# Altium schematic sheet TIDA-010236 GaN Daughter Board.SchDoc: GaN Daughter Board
size A3; DrawnBy: Hely Zhang; Engineer: Hely Zhang; DocumentNumber: 1; Revision: B; SheetNumber: 1; SheetTotal: 1; PageSetup: Record=PageOptions¦CenterHorizontal=True¦CenterVertical=True¦PrintScale=0.69¦XCorrection=1.00¦YCorrection=1.00¦PrintKind=0¦BorderSize=5000000¦LeftOffset=0¦BottomOffset=0¦Orientation=2¦PaperLength=1000¦PaperWidth=1000¦Scale=100¦PaperSource=15¦PrintQuality=600¦MediaType=1¦DitherType=10¦PaperKind=Letter¦PrintScaleMode=1
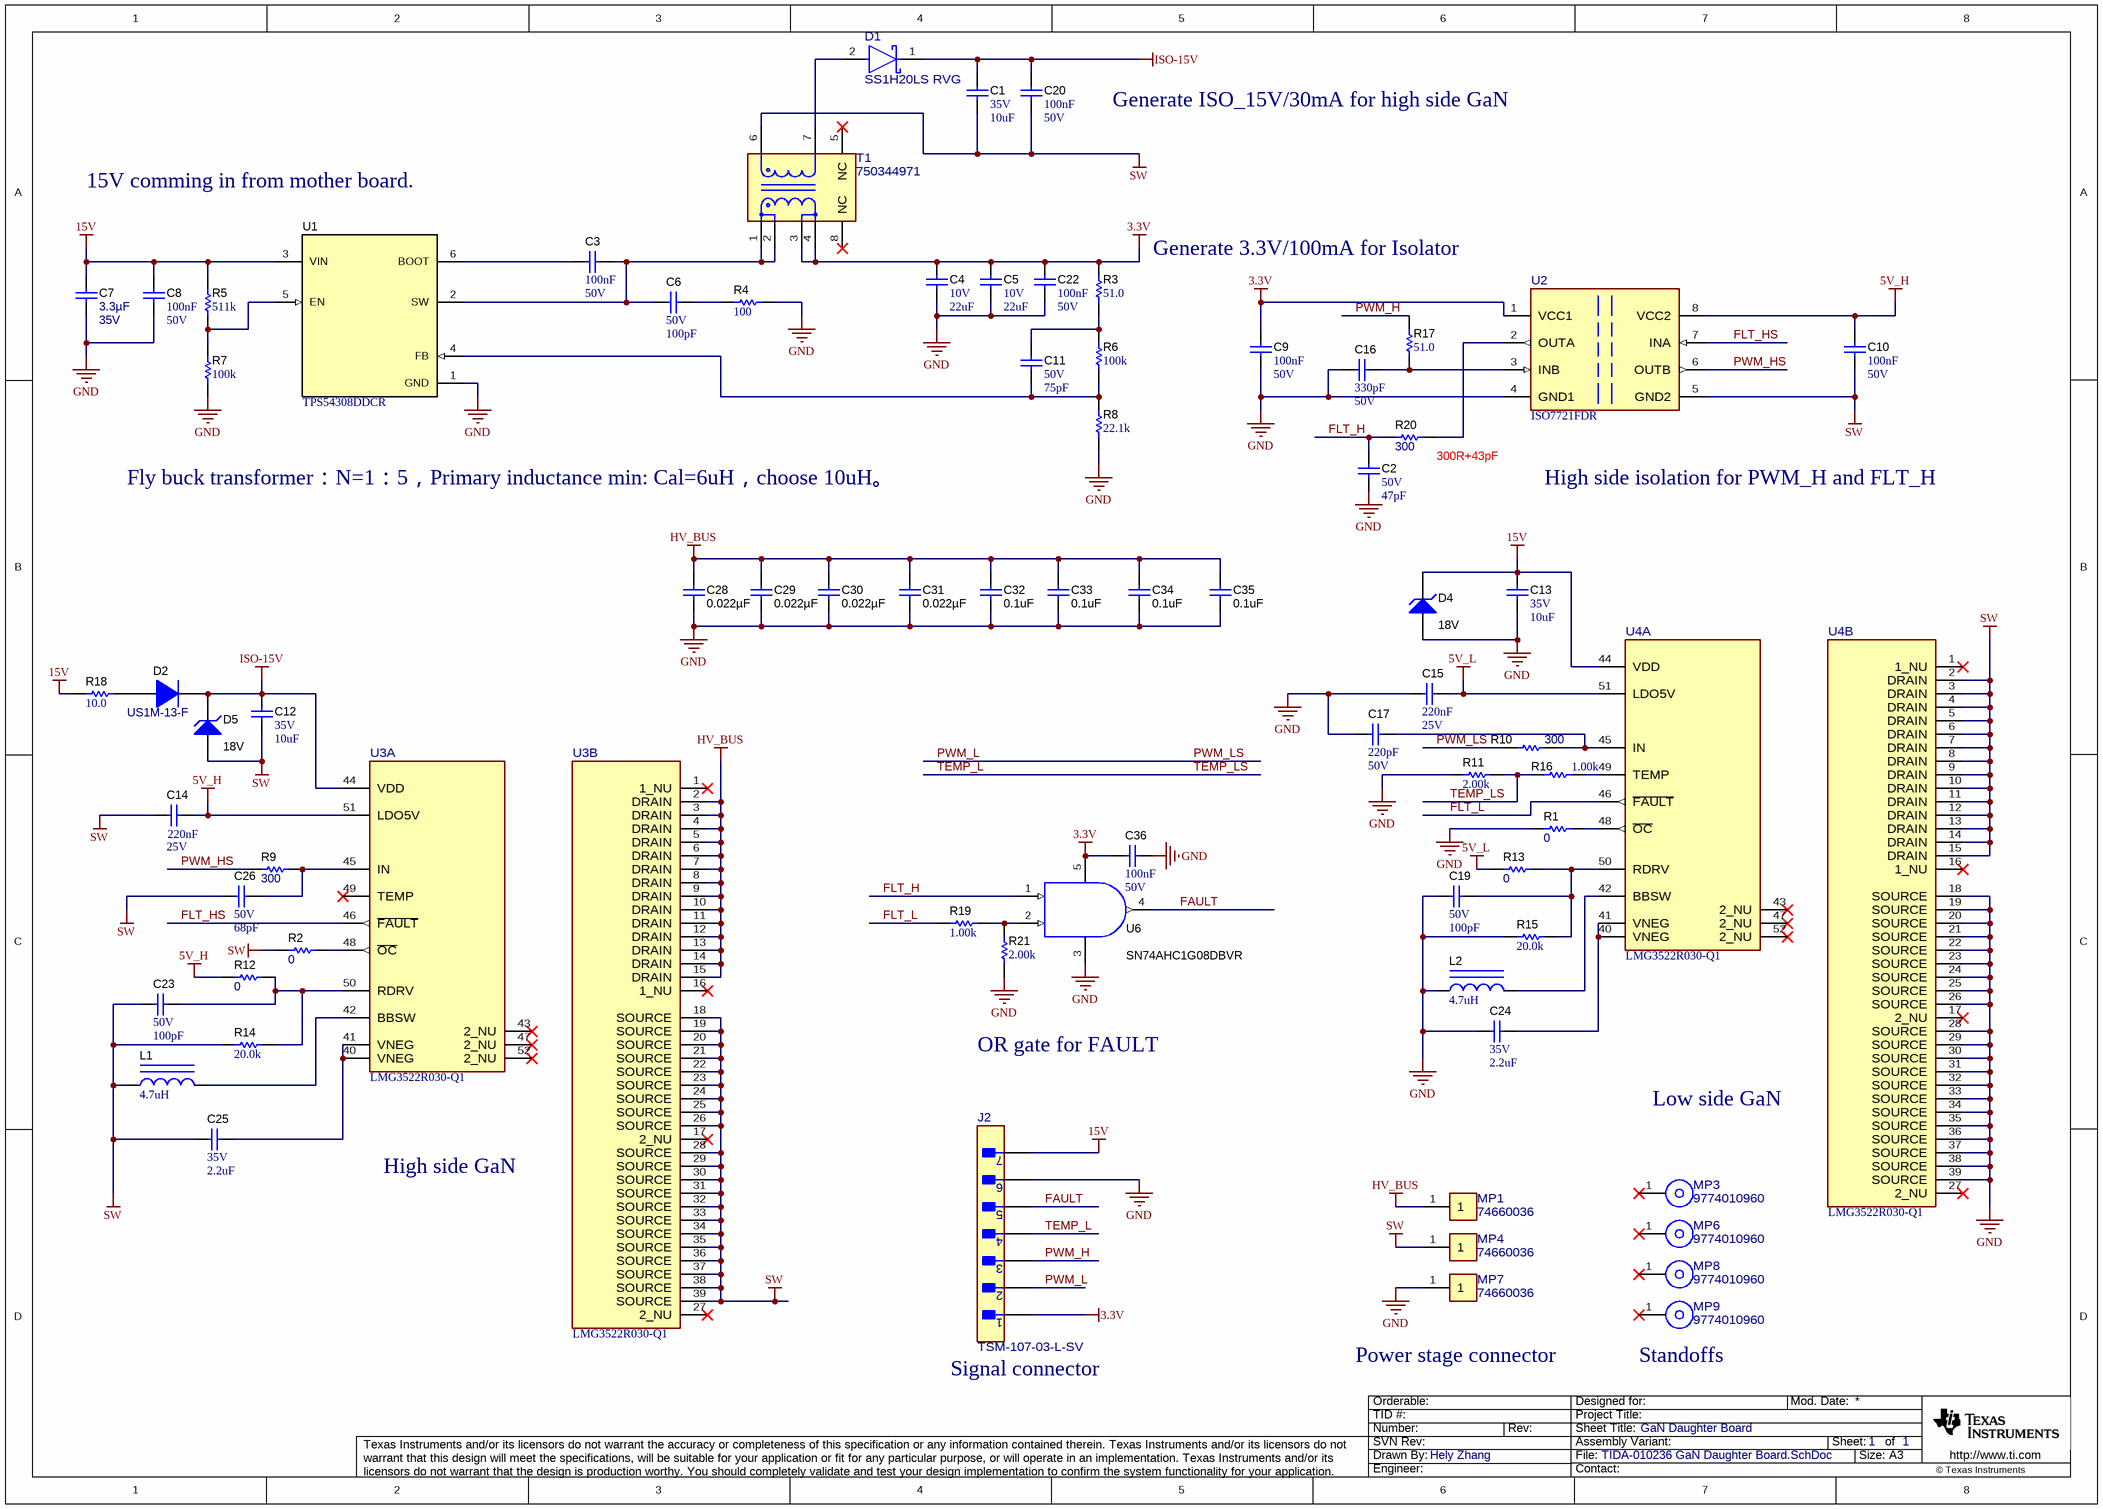
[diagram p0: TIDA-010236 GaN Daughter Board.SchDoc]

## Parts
C1  VDC_V: 35V  ValueDisplayed: 10uF  [1206_190]  (hidden comment: C3216X7R1V106M160AC)
C2  VDC_V: 50V  ValueDisplayed: 47pF  [0603]  (hidden comment: GRM1885C1H470JA01D)
C3  Cap_F: 100nF  VDC_V: 50V  [0603]  (hidden comment: 06035C104JAT2A)
C4  VDC_V: 10V  ValueDisplayed: 22uF  [1206_180]  (hidden comment: GRM31CR71A226ME15L)
C5  VDC_V: 10V  ValueDisplayed: 22uF  [1206_180]  (hidden comment: GRM31CR71A226ME15L)
C6  VDC_V: 50V  ValueDisplayed: 100pF  [0603]  (hidden comment: GRM1885C1H101JA01D)
C7  Cap_F: 3.3µF  VDC_V: 35V  [0805_HV]  (hidden comment: CGA4J1X7R1V335K125AC)
C8  Cap_F: 100nF  VDC_V: 50V  [0603]  (hidden comment: 06035C104JAT2A)
C9  Cap_F: 100nF  VDC_V: 50V  [0603]  (hidden comment: 06035C104JAT2A)
C10  Cap_F: 100nF  VDC_V: 50V  [0603]  (hidden comment: 06035C104JAT2A)
C11  VDC_V: 50V  ValueDisplayed: 75pF  [0603]  (hidden comment: GRM1885C1H750JA01D)
C12  VDC_V: 35V  ValueDisplayed: 10uF  [1206_190]  (hidden comment: C3216X7R1V106M160AC)
C13  VDC_V: 35V  ValueDisplayed: 10uF  [1206_190]  (hidden comment: C3216X7R1V106M160AC)
C14  Cap_F: 220nF  VDC_V: 25V  [0603]  (hidden comment: GRM188R71E224KA88D)
C15  Cap_F: 220nF  VDC_V: 25V  [0603]  (hidden comment: GRM188R71E224KA88D)
C16  Cap_F: 330pF  VDC_V: 50V  [0603]  (hidden comment: C0603C331K5RACTU)
C17  Cap_F: 220pF  VDC_V: 50V  [0603]  (hidden comment: GRM188R71H221KA01D)
C19  VDC_V: 50V  ValueDisplayed: 100pF  [0603]  (hidden comment: GRM1885C1H101JA01D)
C20  Cap_F: 100nF  VDC_V: 50V  [0603]  (hidden comment: 06035C104JAT2A)
C22  Cap_F: 100nF  VDC_V: 50V  [0603]  (hidden comment: 06035C104JAT2A)
C23  VDC_V: 50V  ValueDisplayed: 100pF  [0603]  (hidden comment: GRM1885C1H101JA01D)
C24  VDC_V: 35V  ValueDisplayed: 2.2uF  [0603]  (hidden comment: GRM188R6YA225KA12D)
C25  VDC_V: 35V  ValueDisplayed: 2.2uF  [0603]  (hidden comment: GRM188R6YA225KA12D)
C26  VDC_V: 50V  ValueDisplayed: 68pF  [0603]  (hidden comment: GCM1885C1H680JA16D)
C28  ValueDisplayed: 0.022µF  [1206_190]  (hidden comment: C1206C223KDRACTU)
C29  ValueDisplayed: 0.022µF  [1206_190]  (hidden comment: C1206C223KDRACTU)
C30  ValueDisplayed: 0.022µF  [1206_190]  (hidden comment: C1206C223KDRACTU)
C31  ValueDisplayed: 0.022µF  [1206_190]  (hidden comment: C1206C223KDRACTU)
C32  ValueDisplayed: 0.1uF  [1812_254]  (hidden comment: C1812W104KDRACTU)
C33  ValueDisplayed: 0.1uF  [1812_254]  (hidden comment: C1812W104KDRACTU)
C34  ValueDisplayed: 0.1uF  [1812_254]  (hidden comment: C1812W104KDRACTU)
C35  ValueDisplayed: 0.1uF  [1812_254]  (hidden comment: C1812W104KDRACTU)
C36  Cap_F: 100nF  VDC_V: 50V  [0603]  (hidden comment: 06035C104JAT2A)
D1  SS1H20LS RVG  [FP-SS1H20LS RVG_SOD123HE-MFG]
D2  US1M-13-F  [SMA]
D4  value 18V  [SOD-123]  (hidden comment: BZT52C18-7-F)
D5  value 18V  [SOD-123]  (hidden comment: BZT52C18-7-F)
J2  TSM-107-03-L-SV  [FP-TSM-107-03-L-SV_HDR7-MFG]
L1  ValueDisplayed: 4.7uH  [DFE252010C]  (hidden comment: 1269AS-H-4R7M=P2)
L2  ValueDisplayed: 4.7uH  [DFE252010C]  (hidden comment: 1269AS-H-4R7M=P2)
MP1  74660036  [FP-74660036_SMT_BUSH-MFG]
MP3  9774010960  [FP-9774010960_SPACER_ROUND-MFG]
MP4  74660036  [FP-74660036_SMT_BUSH-MFG]
MP6  9774010960  [FP-9774010960_SPACER_ROUND-MFG]
MP7  74660036  [FP-74660036_SMT_BUSH-MFG]
MP8  9774010960  [FP-9774010960_SPACER_ROUND-MFG]
MP9  9774010960  [FP-9774010960_SPACER_ROUND-MFG]
R1  ValueDisplayed: 0  [0402]  (hidden comment: RC0402JR-070RL)
R2  ValueDisplayed: 0  [0402]  (hidden comment: RC0402JR-070RL)
R3  ValueDisplayed: 51.0  [0603]  (hidden comment: RC0603FR-0751RL)
R4  ValueDisplayed: 100  [0603]  (hidden comment: RC0603FR-07100RL)
R5  ValueDisplayed: 511k  [0603]  (hidden comment: RC0603FR-07511KL)
R6  ValueDisplayed: 100k  [0603]  (hidden comment: RC0603FR-07100KL)
R7  ValueDisplayed: 100k  [0603]  (hidden comment: RC0603FR-07100KL)
R8  ValueDisplayed: 22.1k  [0603]  (hidden comment: RC0603FR-0722K1L)
R9  ValueDisplayed: 300  [0603]  (hidden comment: RC0603FR-07300RL)
R10  ValueDisplayed: 300  [0603]  (hidden comment: RC0603FR-07300RL)
R11  ValueDisplayed: 2.00k  [0603]  (hidden comment: RC0603FR-072KL)
R12  ValueDisplayed: 0  [0402]  (hidden comment: RC0402JR-070RL)
R13  ValueDisplayed: 0  [0402]  (hidden comment: RC0402JR-070RL)
R14  ValueDisplayed: 20.0k  [0603]  (hidden comment: RC0603FR-0720KL)
R15  ValueDisplayed: 20.0k  [0603]  (hidden comment: RC0603FR-0720KL)
R16  ValueDisplayed: 1.00k  [0603]  (hidden comment: RC0603FR-071KL)
R17  ValueDisplayed: 51.0  [0603]  (hidden comment: RC0603FR-0751RL)
R18  ValueDisplayed: 10.0  [1206]  (hidden comment: RC1206FR-0710RL)
R19  ValueDisplayed: 1.00k  [0603]  (hidden comment: RC0603FR-071KL)
R20  ValueDisplayed: 300  [0603]  (hidden comment: RC0603FR-07300RL)
R21  ValueDisplayed: 2.00k  [0603]  (hidden comment: RC0603FR-072KL)
T1  750344971  [FP-750344971_SMT_XFRMR_14MM0_10MM0-MFG]
U1  TPS54308DDCR  [DDC0006A_N]
U2  ISO7721FDR  [D0008A-MFG]
U3  LMG3522R030-Q1  [RQS0052C-C01-MFG]  (parts A,B of 2)
U4  LMG3522R030-Q1  [RQS0052C-C01-MFG]  (parts A,B of 2)
U6  SN74AHC1G08DBVR  [DBV0005A_N]

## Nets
3.3V: C4.1 C5.1 C9.1 C22.1 C36.1 J2.1 R3.2 T1.3 T1.4 U2.1(VCC1) U6.5(V+)
5V_H: C10.1 C14.2 R12.1 U2.8(VCC2) U3.51(LDO5V)
5V_L: C15.2 R13.1 U4.51(LDO5V)
15V: C7.1 C8.1 C13.1 D4.1(K) J2.7 R5.2 R18.1 U1.3(VIN) U4.44(VDD)
GND: C2.2 C4.2 C5.2 C7.2 C8.2 C9.2 C13.2 C15.1 C16.2 C17.2 C19.2 C22.2 C24.2 C28.2 C29.2 C30.2 C31.2 C32.2 C33.2 C34.2 C35.2 C36.2 D4.2(A) J2.6 L2.1 MP7.1 R1.1 R4.2 R7.1 R8.1 R11.2 R15.1 R21.1 U1.1(GND) U2.4(GND1) U4.18(SOURCE) U4.19(SOURCE) U4.20(SOURCE) U4.21(SOURCE) U4.22(SOURCE) U4.23(SOURCE) U4.24(SOURCE) U4.25(SOURCE) U4.26(SOURCE) U4.28(SOURCE) U4.29(SOURCE) U4.30(SOURCE) U4.31(SOURCE) U4.32(SOURCE) U4.33(SOURCE) U4.34(SOURCE) U4.35(SOURCE) U4.36(SOURCE) U4.37(SOURCE) U4.38(SOURCE) U4.39(SOURCE) U6.3(V-)
HV_BUS: C28.1 C29.1 C30.1 C31.1 C32.1 C33.1 C34.1 C35.1 MP1.1 U3.2(DRAIN) U3.3(DRAIN) U3.4(DRAIN) U3.5(DRAIN) U3.6(DRAIN) U3.7(DRAIN) U3.8(DRAIN) U3.9(DRAIN) U3.10(DRAIN) U3.11(DRAIN) U3.12(DRAIN) U3.13(DRAIN) U3.14(DRAIN) U3.15(DRAIN)
ISO-15V: C1.1 C12.1 C20.1 D1.1(CATHODE) D2.1(K) D5.1(K) U3.44(VDD)
SW: C1.2 C10.2 C12.2 C14.1 C20.2 C23.2 C25.2 C26.2 D5.2(A) L1.1 MP4.1 R2.1 R14.1 T1.6 U2.5(GND2) U3.18(SOURCE) U3.19(SOURCE) U3.20(SOURCE) U3.21(SOURCE) U3.22(SOURCE) U3.23(SOURCE) U3.24(SOURCE) U3.25(SOURCE) U3.26(SOURCE) U3.28(SOURCE) U3.29(SOURCE) U3.30(SOURCE) U3.31(SOURCE) U3.32(SOURCE) U3.33(SOURCE) U3.34(SOURCE) U3.35(SOURCE) U3.36(SOURCE) U3.37(SOURCE) U3.38(SOURCE) U3.39(SOURCE) U4.2(DRAIN) U4.3(DRAIN) U4.4(DRAIN) U4.5(DRAIN) U4.6(DRAIN) U4.7(DRAIN) U4.8(DRAIN) U4.9(DRAIN) U4.10(DRAIN) U4.11(DRAIN) U4.12(DRAIN) U4.13(DRAIN) U4.14(DRAIN) U4.15(DRAIN)
FAULT: J2.5 U6.4(Y)
FLT_H: C2.1 R20.2 U6.1(A)
FLT_HS: U2.7(INA) U3.46(~{FAULT})
FLT_L: R19.1 U4.46(~{FAULT})
PWM_H: J2.3 R17.1
PWM_HS: R9.2 U2.6(OUTB)
PWM_L: J2.2 R10.2  [also labelled PWM_LS]
TEMP_L: J2.4 R11.1 R16.1  [also labelled TEMP_LS]
NetC3_1: C3.1 C6.2 T1.1 T1.2 U1.2(SW)
NetC3_2: C3.2 U1.6(BOOT)
NetC6_1: C6.1 R4.1
NetC11_1: C11.1 R3.1 R6.2
NetC11_2: C11.2 R6.1 R8.2 U1.4(FB)
NetC16_1: C16.1 R17.2 U2.3(INB)
NetC17_1: C17.1 R10.1 U4.45(IN)
NetC19_1: C19.1 R13.2 R15.2 U4.50(RDRV)
NetC23_1: C23.1 R12.2 R14.2 U3.50(RDRV)
NetC24_1: C24.1 U4.40(VNEG) U4.41(VNEG)
NetC25_1: C25.1 U3.40(VNEG) U3.41(VNEG)
NetC26_1: C26.1 R9.1 U3.45(IN)
NetD1_2: D1.2(ANODE) T1.7
NetD2_2: D2.2(A) R18.2
NetL1_2: L1.2 U3.42(BBSW)
NetL2_2: L2.2 U4.42(BBSW)
NetR1_2: R1.2 U4.48(~{OC})
NetR2_2: R2.2 U3.48(~{OC})
NetR5_1: R5.1 R7.2 U1.5(EN)
NetR16_2: R16.2 U4.49(TEMP)
NetR19_2: R19.2 R21.2 U6.2(B)
NetR20_1: R20.1 U2.2(OUTA)

Not connected (* = marked no-connect by the designer): MP3 1*; MP6 1*; MP8 1*; MP9 1*; T1 5(NC)* 8(NC)*; U3 1(1_NU)* 16(1_NU)* 17(2_NU)* 27(2_NU)* 43(2_NU)* 47(2_NU)* 49(TEMP)* 52(2_NU)*; U4 1(1_NU)* 16(1_NU)* 17(2_NU)* 27(2_NU)* 43(2_NU)* 47(2_NU)* 52(2_NU)*

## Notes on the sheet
- Generate ISO_15V/30mA for high side GaN
- 15V comming in from mother board.
- Generate 3.3V/100mA for Isolator
- Fly buck transformer：N=1：5，Primary inductance min: Cal=6uH，choose 10uH。
- (near R20) 300R+43pF
- High side isolation for PWM_H and FLT_H
- OR gate for FAULT
- Low side GaN
- High side GaN
- (near J2) Signal connector
- Power stage connector
- (near MP9) Standoffs

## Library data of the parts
C1 C12 C13 = CMP-0008706-2: CAP, CERM, 10 uF, 35 V, +/- 20%, X7R, 1206_190; Manufacturer: TDK; TaMin_C: -55°C; Polarized: N; SizeAreaWB_mm2: 10.92; Value1: Unknown; U/M: EA; Value: 10uF; TaMax_C: 125°C; SizeZ_mm: 1.9; SizeX_mm: 3.2; SizeY_mm: 1.6; Cap_Case: 1206; SizeArea_mm2: 5.12; Cap_F: 10µF; AEC Category: Q200
C2 = CMP-0007220-2: CAP, CERM, 47 pF, 50 V, +/- 5%, C0G/NP0, 0603; Manufacturer: MuRata; TaMin_C: -55°C; Polarized: N; SizeAreaWB_mm2: 4.68; Value1: Unknown; U/M: EA; Value: 47pF; TaMax_C: 125°C; SizeZ_mm: 1; SizeX_mm: 1.6; SizeY_mm: 0.8; SizeArea_mm2: 1.28; AEC Category: Q200
C3 C8-C10 C20 C22 C36 = CMP-0083854-1: CAP, CERM, 0.1 µF, 50 V,+/- 5%, X7R, 0603; Manufacturer: AVX; TaMin_C: -55°C; Polarized: N; Green_Lifecycle: Active; SizeAreaWB_mm2: 4.68; Green_REACh: Passed; U/M: EA; Value: 0.1uF; TaMax_C: 125°C; SizeZ_mm: 1; SizeX_mm: 1.6; SizeY_mm: 0.8; SizeArea_mm2: 1.28; AEC Category: Q200; ValueDisplayed: 0.1µF
C4 C5 = CMP-0008960-1: CAP, CERM, 22 uF, 10 V, +/- 20%, X7R, 1206; Manufacturer: MuRata; TaMin_C: -55°C; Polarized: N; SizeAreaWB_mm2: 10.92; Value1: Unknown; U/M: EA; Value: 22uF; TaMax_C: 125°C; SizeZ_mm: 1.8; SizeX_mm: 3.2; SizeY_mm: 1.6; Cap_Case: 1206; SizeArea_mm2: 5.12; Cap_F: 22µF; AEC Category: Q200
C6 C19 C23 = CMP-0007171-4: CAP, CERM, 100 pF, 50 V, +/- 5%, C0G/NP0, 0603; Manufacturer: MuRata; TaMin_C: -55°C; Polarized: N; SizeAreaWB_mm2: 4.68; Value1: Unknown; U/M: EA; Value: 100pF; TaMax_C: 125°C; SizeZ_mm: 1; SizeX_mm: 1.6; SizeY_mm: 0.8; SizeArea_mm2: 1.28; AEC Category: Q200
C7 = CMP-0007963-2: CAP, CERM, 3.3 uF, 35 V, +/- 10%, X7R, AEC-Q200 Grade 1, 0805; Manufacturer: TDK; TaMin_C: -55°C; ESR_ohm: 2.798m; Polarized: N; SizeAreaWB_mm2: 6.75; Value1: 0.002798 ohm; U/M: EA; Value: 3.3uF; TaMax_C: 125°C; SizeZ_mm: 1.45; SizeX_mm: 2; SizeY_mm: 1.25; Cap_Case: 0805; SizeArea_mm2: 2.5; AEC Qualified: Y; IRMS_A: 3.90156A; AEC Grade: 1; AEC Category: Q200
C11 = CMP-0007230-4: CAP, CERM, 75 pF, 50 V, +/- 5%, C0G/NP0, 0603; Manufacturer: MuRata; TaMin_C: -55°C; Polarized: N; SizeAreaWB_mm2: 4.68; Value1: Unknown; U/M: EA; Value: 75pF; TaMax_C: 125°C; SizeZ_mm: 1; SizeX_mm: 1.6; SizeY_mm: 0.8; SizeArea_mm2: 1.28; AEC Category: Q200
C14 C15 = CMP-0007415-1: CAP, CERM, 0.22 uF, 25 V, +/- 10%, X7R, 0603; Manufacturer: MuRata; TaMin_C: -55°C; Polarized: N; SizeAreaWB_mm2: 4.68; Value1: Unknown; U/M: EA; Value: 0.22uF; TaMax_C: 125°C; SizeZ_mm: 1; SizeX_mm: 1.6; SizeY_mm: 0.8; SizeArea_mm2: 1.28; AEC Category: Q200
C16 = CMP-0006921-4: CAP, CERM, 330 pF, 50 V, +/- 10%, X7R, 0603; Manufacturer: Kemet; TaMin_C: -55°C; Polarized: N; SizeAreaWB_mm2: 4.68; Value1: Unknown; U/M: EA; Value: 330pF; TaMax_C: 125°C; SizeZ_mm: 1; SizeX_mm: 1.6; SizeY_mm: 0.8; SizeArea_mm2: 1.28; AEC Category: Q200
C17 = CMP-0007442-3: CAP, CERM, 220 pF, 50 V, +/- 10%, X7R, 0603; Manufacturer: MuRata; TaMin_C: -55°C; Polarized: N; SizeAreaWB_mm2: 4.68; Value1: Unknown; U/M: EA; Value: 220pF; TaMax_C: 125°C; SizeZ_mm: 1; SizeX_mm: 1.6; SizeY_mm: 0.8; SizeArea_mm2: 1.28; AEC Category: Q200
C24 C25 = CMP-0007356-3: CAP, CERM, 2.2 uF, 35 V, +/- 10%, X5R, 0603; Manufacturer: MuRata; TaMin_C: -55°C; Polarized: N; SizeAreaWB_mm2: 4.68; Value1: Unknown; U/M: EA; Value: 2.2uF; TaMax_C: 85°C; SizeZ_mm: 1; SizeX_mm: 1.6; SizeY_mm: 0.8; SizeArea_mm2: 1.28; Cap_F: 2.2µF; AEC Category: Q200
C26 = CMP-0007129-3: CAP, CERM, 68 pF, 50 V, +/- 5%, C0G/NP0, AEC-Q200 Grade 1, 0603; Manufacturer: MuRata; TaMin_C: -55°C; Polarized: N; SizeAreaWB_mm2: 4.68; Value1: Unknown; U/M: EA; Value: 68pF; TaMax_C: 125°C; SizeZ_mm: 1; SizeX_mm: 1.6; SizeY_mm: 0.8; SizeArea_mm2: 1.28; AEC Qualified: Y; AEC Category: Q200
C28-C31 = CMP-0084048-1: CAP, CERM, 0.022 µF, 1000 V,+/- 10%, X7R, AEC-Q200 Grade 1, 1206; Manufacturer: Kemet; Polarized: N; CompType: Capacitor; Value: 0.022uF; U/M: EA; Cap_F: 22nF; VDC_V: 1kV; Value2: 1000V; TaMin_C: -55°C; TaMax_C: 125°C; Cap_Case: 1206; SizeArea_mm2: 5.12; SizeAreaWB_mm2: 10.92; SizeX_mm: 3.2; SizeY_mm: 1.6; SizeZ_mm: 1.9; AEC Category: Q200; AEC Qualified: Y; AEC Grade: 1
C32-C35 = CMP-0009326-2: CAP, CERM, 0.1 uF, 1000 V, +/- 10%, X7R, 1812; Manufacturer: Kemet; Polarized: N; Value: 0.1uF; U/M: EA; Cap_F: 100nF; Value1: Unknown; VDC_V: 1kV; Value2: 1000V; TaMin_C: -55°C; TaMax_C: 125°C; Cap_Case: 1812; AEC Category: Q200; SizeArea_mm2: 14.4; SizeAreaWB_mm2: 23.1; SizeX_mm: 4.5; SizeY_mm: 3.2; SizeZ_mm: 2.54
D1 = CMP-0093179-1: Rectifier Diode Schottky 200V 1A 2-Pin SOD-123HE T/R; Manufacturer: Taiwan Semiconductor; AEC Qualified: No; Peak Reverse Current: 1uA; SizeZ_mm: 0.85mm; TJmax_C: 150°C; Max Surge Forward Current: 30A
D2 = CMP-0076882-1: Diode, Ultrafast, 1000 V, 1 A, SMA; Manufacturer: Diodes Inc.; SizeAreaWB_mm2: 37.3428; Vr_V: 1kV; SizeArea_mm2: 16.3228; TJmax_C: 150°C; AEC Category: Q101; Value: 1000V; SizeZ_mm: 2.87; Green_REACh: Incomplete; Io_A: 1A; Vf_V: 1.7V; SizeY_mm: 2.92; Green_Lifecycle: Not Set; U/M: EA; SizeX_mm: 5.59; RJC_CperW: 30.0
D4 D5 = CMP-0005769-2: Diode, Zener, 18 V, 500 mW, AEC-Q101, SOD-123; Manufacturer: Diodes Inc.; Power_W: 500mW; SizeAreaWB_mm2: 13.095; Value1: 0.5W; RJA_CperW: 338; U/M: EA; SizeZ_mm: 1.35; SizeX_mm: 3.85; SizeY_mm: 1.7; SizeArea_mm2: 6.545; AEC Qualified: Y; AEC Category: Q101
J2 = CMP-0095158-1: Manufacturer: Samtec; SizeZ_mm: 15.06mm; Standoff Height: 1.02mm; Conn Orientation: Vertical; ContactFinish: Gold,Nickel; DUT-Pitch_mm: 2.54mm; AEC Qualified: No; Conn Gender: Male; Row_Count: 1
L1 L2 = CMP-0058910-1: Inductor, Shielded, Metal Composite, 4.7 uH, 1.2 A, 0.25 ohm, SMD; Manufacturer: MuRata Toko; Isat: 1.6A @ 30% inductance drop; Irms: 1.2A @ 40C rise; SizeAreaWB_mm2: 11.84; DCR_ohm: 0.25; Value: 4.7uH; Imax_A: 1.2A; SizeZ_mm: 1; SizeX_mm: 2.7; SizeY_mm: 2.2; SizeArea_mm2: 5.94; Ind_H: 4.7µH; AEC Qualified: N; AEC Category: Q200
MP1 MP4 MP7 = CMP-0095159-2: 1 Pin Screw Terminal, Power Tap M3, 6mm, Surface Mount; Manufacturer: Wurth Electronics; SizeZ_mm: 6.1mm; AEC Qualified: No
MP3 MP6 MP8 MP9 = CMP-0097508-1: Manufacturer: Wurth Electronics; AEC Qualified: No; Is Female: yes; SizeZ_mm: 1.1mm
R1 R2 R12 R13 = CMP-0027004-2: RES, 0, 5%, 0.063 W, 0402; Manufacturer: Yageo America; Power_W: 63mW; TempCo: 200 ppm/C; Value_Code: 0000; U/M: EA; Value: 0; EIA_Code: E24; SizeX_mm: 1; SizeY_mm: 0.5; SizeZ_mm: 0.6; Value2: 0.063W; VDC_V: 50V; AEC Category: Q200
R3 R17 = CMP-0023169-5: RES, 51.0, 1%, 0.1 W, 0603; Manufacturer: Yageo; Power_W: 100mW; TempCo: 100 ppm/C; Value_Code: 51R0; Value: 51.0; Res_ohm: 51; SizeX_mm: 1.6; SizeY_mm: 0.8; SizeZ_mm: 1; Value2: 0.1W; SizeArea_mm2: 1.28; AEC Qualified: N; VDC_V: 75V; AEC Category: Q200; SizeAreaWB_mm2: 4.68
R4 = CMP-0022736-4: RES, 100, 1%, 0.1 W, 0603; Manufacturer: Yageo; Power_W: 100mW; TempCo: 100 ppm/C; Value_Code: 100R; Value: 100; EIA_Code: E96; SizeX_mm: 1.6; SizeY_mm: 0.8; SizeZ_mm: 1; Value2: 0.1W; SizeArea_mm2: 1.28; AEC Qualified: N; VDC_V: 75V; AEC Category: Q200; SizeAreaWB_mm2: 4.68
R5 = CMP-0023164-4: RES, 511 k, 1%, 0.1 W, 0603; Manufacturer: Yageo; Power_W: 100mW; TempCo: 100 ppm/C; Value: 511k; SizeX_mm: 1.6; SizeY_mm: 0.8; SizeZ_mm: 1; Value2: 0.1W; SizeArea_mm2: 1.28; AEC Qualified: N; VDC_V: 75V; AEC Category: Q200; EIA_Code: E96; SizeAreaWB_mm2: 4.68
R6 R7 = CMP-0022735-5: RES, 100 k, 1%, 0.1 W, 0603; Manufacturer: Yageo; Power_W: 100mW; TempCo: 100 ppm/C; Value: 100k; EIA_Code: E96; SizeX_mm: 1.6; SizeY_mm: 0.8; SizeZ_mm: 1; Value2: 0.1W; SizeArea_mm2: 1.28; AEC Qualified: N; VDC_V: 75V; AEC Category: Q200; SizeAreaWB_mm2: 4.68
R8 = CMP-0022923-5: RES, 22.1 k, 1%, 0.1 W, 0603; Manufacturer: Yageo; Power_W: 100mW; TempCo: 100 ppm/C; Value_Code: 22k1; Value: 22.1k; EIA_Code: E96; SizeX_mm: 1.6; SizeY_mm: 0.8; SizeZ_mm: 1; Value2: 0.1W; SizeArea_mm2: 1.28; AEC Qualified: N; VDC_V: 75V; AEC Category: Q200; SizeAreaWB_mm2: 4.68
R9 R10 R20 = CMP-0023013-5: RES, 300, 1%, 0.1 W, 0603; Manufacturer: Yageo; Power_W: 100mW; TempCo: 100 ppm/C; Value_Code: 300R; Value: 300; SizeX_mm: 1.6; SizeY_mm: 0.8; SizeZ_mm: 1; Value2: 0.1W; SizeArea_mm2: 1.28; AEC Qualified: N; VDC_V: 75V; AEC Category: Q200; SizeAreaWB_mm2: 4.68
R11 R21 = CMP-0023000-5: RES, 2.00 k, 1%, 0.1 W, 0603; Manufacturer: Yageo; Power_W: 100mW; TempCo: 100 ppm/C; Value_Code: 2k00; Value: 2.00k; EIA_Code: E96; Res_ohm: 2k; SizeX_mm: 1.6; SizeY_mm: 0.8; SizeZ_mm: 1; Value2: 0.1W; SizeArea_mm2: 1.28; AEC Qualified: N; VDC_V: 75V; AEC Category: Q200; SizeAreaWB_mm2: 4.68
R14 R15 = CMP-0022906-5: RES, 20.0 k, 1%, 0.1 W, 0603; Manufacturer: Yageo; Power_W: 100mW; TempCo: 100 ppm/C; Value_Code: 20k0; Value: 20.0k; EIA_Code: E96; Res_ohm: 20k; SizeX_mm: 1.6; SizeY_mm: 0.8; SizeZ_mm: 1; Value2: 0.1W; SizeArea_mm2: 1.28; AEC Qualified: N; VDC_V: 75V; AEC Category: Q200; SizeAreaWB_mm2: 4.68
R16 R19 = CMP-0022895-5: RES, 1.00 k, 1%, 0.1 W, 0603; Manufacturer: Yageo; Power_W: 100mW; TempCo: 100 ppm/C; Value_Code: 1k00; Value: 1.00k; EIA_Code: E96; Res_ohm: 1k; SizeX_mm: 1.6; SizeY_mm: 0.8; SizeZ_mm: 1; Value2: 0.1W; SizeArea_mm2: 1.28; AEC Qualified: N; VDC_V: 75V; AEC Category: Q200; SizeAreaWB_mm2: 4.68
R18 = CMP-0017851-1: RES, 10.0, 1%, 0.25 W, 1206; Manufacturer: Yageo America; Power_W: 250mW; TempCo: 200 ppm/C; Value_Code: 10R0; U/M: EA; Value: 10.0; EIA_Code: E96; Res_ohm: 10; SizeX_mm: 3.2; SizeY_mm: 1.6; SizeZ_mm: 1.35; Value2: 0.25W; SizeArea_mm2: 5.12; VDC_V: 200V; AEC Category: Q200
T1 = CMP-0095161-1: Transformer, 1:5, 1500VAC, 10uH, 14x10x5mm; Manufacturer: Wurth Electronics; Ind_H: 10µH; Voltage_Isolation_Vrms: 1.5kV; Frequency_Fixed: 350kHz; AEC Qualified: No; SizeZ_mm: 5mm
U1 = CMP-0013278-3: 4.5-V to 28-V Input, 3-A Output Synchronous Step-Down Converter, DDC0006A (SOT-6); Alternate PartNumber: TPS54308DDCT; Manufacturer: Texas Instruments; SizeZ_mm: 0.87; SizeX_mm: 1.65; SizeY_mm: 2.95; SizeArea_mm2: 4.8675; CompType: IC; U/M: EA; SizeAreaWB_mm2: 10.4675
U2 = CMP-0089949-1: Low Speed, General Purpose, Robust EMC, Dual-Channel Digital Isolators; Manufacturer: Texas Instruments; TJmax_C: +150°C; TaMin_C: -40°C; SizeZ_mm: 1.75mm; Min Supply Voltage: 1.71V; Standoff Height: 0.11mm; AEC Qualified: Yes; TaMax_C: +125°C; AEC Grade: Grade 1; Max Supply Voltage: 5.5V; Interface: LVCMOS
U3 U4 = CMP-0094891-1: 650-V 30-mΩ GaN FET with Integrated Driver, Protection, and Temperature Reporting; Manufacturer: Texas Instruments; Max Supply Voltage: 18V; TaMax_C: +125°C; TaMin_C: -40°C; Nominal Supply Current: 16mA; Number Of Outputs: 1; Standoff Height: 0mm; Min Supply Voltage: 7.5V; TJmax_C: +150°C; AEC Grade: Grade 1; SizeZ_mm: 1mm; Output Voltage: 520V; AEC Qualified: Yes
U6 = SN74AHC1G08DBVR: Single 2-Input Positive-AND Gate, DBV0005A; Alternate PartNumber: SN74AHC1G08DBVT; Manufacturer: Texas Instruments; CompType: IC; SizeArea_mm2: 8.12; SizeAreaWB_mm2: 14.82; SizeX_mm: 2.8; SizeY_mm: 2.9; SizeZ_mm: 1.45; U/M: EA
